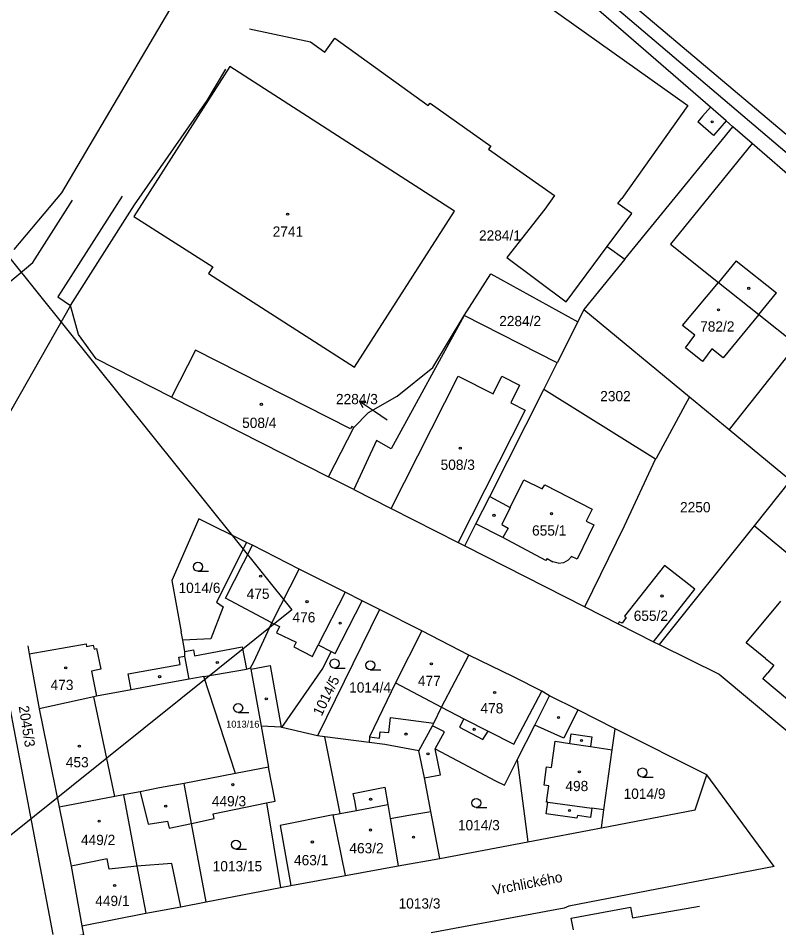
# Model space of a CAD drawing. Extents: x -793666 to -785424, y -1118958 to -1108761.
# Drawn here: x -791983.5 to -791857.2, y -1109795.1 to -1109644.2 of the extents above; entities that cross this region are included whole.
import ezdxf

# ---------------------------------------------------------------- set-up
doc = ezdxf.new("R2010")
doc.units = 0
for name, color, linetype in [('1_2000 - úřady', 7, 'Continuous'), ('Hranice parcel', 7, 'Continuous'), ('Parcelní čísla', 7, 'Continuous'), ('Pop  PČ popisy', 7, 'Continuous'), ('Vnitřní kresba', 7, 'Continuous'), ('Značky budov', 7, 'Continuous'), ('Značky kultur', 7, 'Continuous')]:
    doc.layers.add(name, color=color, linetype=linetype)

msp = doc.modelspace()

# ---------------------------------------------------------------- linework, layer by layer
at = {"layer": '1_2000 - úřady'}
msp.add_lwpolyline([(-791938.08, -1109742.36), (-792598.01, -1110271.46), (-792786.15, -1110036.8), (-792126.22, -1109507.7)], close=True, dxfattribs=at)
at = {"layer": 'Hranice parcel'}
for p, q in [((-791882.76, -1109684.15), (-791864.85, -1109662.19)), ((-791861.64, -1109664.97), (-791864.85, -1109662.19)), ((-791831.46, -1109691.13), (-791861.64, -1109664.97)), ((-791882.76, -1109684.15), (-791889.58, -1109692.5)), ((-791974.78, -1109691.82), (-791985.69, -1109711.05)), ((-791894.03, -1109701.35), (-791909.43, -1109693.51)), ((-791889.58, -1109692.5), (-791890.6, -1109694.54)), ((-791889.58, -1109692.5), (-791872.04, -1109706.99)), ((-791890.6, -1109694.54), (-791894.03, -1109701.35)), ((-791854.32, -1109698.31), (-791865.49, -1109712.41)), ((-791958, -1109707.05), (-791970.54, -1109700.7)), ((-791896.25, -1109705.77), (-791894.03, -1109701.35)), ((-791877.68, -1109717.35), (-791896.25, -1109705.77)), ((-791958, -1109707.05), (-791931.97, -1109720.25)), ((-791872.04, -1109706.99), (-791877.61, -1109717.21)), ((-791872.04, -1109706.99), (-791865.49, -1109712.41)), ((-791927.77, -1109712.09), (-791925.35, -1109709.61)), ((-791931.97, -1109720.25), (-791927.77, -1109712.09)), ((-791865.49, -1109712.41), (-791855.28, -1109720.85)), ((-791877.61, -1109717.21), (-791877.68, -1109717.35)), ((-791927.74, -1109722.4), (-791931.97, -1109720.25)), ((-791855.28, -1109720.85), (-791861.3, -1109728.39)), ((-791953.47, -1109727.24), (-791957.98, -1109737.48)), ((-791945.56, -1109731.16), (-791953.47, -1109727.24)), ((-791861.3, -1109728.39), (-791877.07, -1109748.13)), ((-791837.39, -1109748.55), (-791861.3, -1109728.39)), ((-791909.36, -1109731.72), (-791889.45, -1109741.84)), ((-791957.98, -1109737.48), (-791956.42, -1109746.03)), ((-791923.52, -1109742.28), (-791926.4, -1109740.83)), ((-791889.45, -1109741.84), (-791883.9, -1109744.66)), ((-791923.52, -1109742.28), (-791933.8, -1109763.25)), ((-791916.48, -1109745.84), (-791923.52, -1109742.28)), ((-791883.9, -1109744.66), (-791878.03, -1109747.64)), ((-791956.17, -1109747.38), (-791956.42, -1109746.03)), ((-791908.66, -1109749.89), (-791916.48, -1109745.84)), ((-791878.03, -1109747.64), (-791877.07, -1109748.13)), ((-791977.67, -1109796.24), (-791985.8, -1109753.42)), ((-791952.67, -1109753.41), (-791955.12, -1109753.87)), ((-791947.39, -1109769.52), (-791952.67, -1109753.41)), ((-791980, -1109758.8), (-791976.67, -1109775.1)), ((-791943.16, -1109761.65), (-791941.92, -1109768.48)), ((-791933.8, -1109763.25), (-791939.71, -1109761.86)), ((-791932.57, -1109763.41), (-791933.8, -1109763.25)), ((-791869.18, -1109769.73), (-791884.37, -1109762.08)), ((-791925.23, -1109764.37), (-791932.57, -1109763.41)), ((-791916.05, -1109770.26), (-791916.98, -1109765.74)), ((-791900.65, -1109767.25), (-791898.88, -1109780.87)), ((-791941.92, -1109768.48), (-791947.39, -1109769.52)), ((-791947.39, -1109769.52), (-791955.94, -1109771.15)), ((-791858, -1109784.94), (-791869.18, -1109769.73)), ((-791954.7, -1109777.79), (-791955.94, -1109771.15)), ((-791976.67, -1109775.1), (-791974.7, -1109784.87)), ((-791942.26, -1109774.38), (-791939.94, -1109788.43)), ((-791952.26, -1109790.84), (-791954.7, -1109777.79)), ((-791898.88, -1109780.87), (-791886.67, -1109778.56)), ((-791913.48, -1109783.61), (-791898.88, -1109780.87)), ((-791974.7, -1109784.87), (-791972.9, -1109794.78)), ((-791952.26, -1109790.84), (-791939.94, -1109788.43)), ((-791956.49, -1109791.62), (-791952.26, -1109790.84))]:
    msp.add_line(p, q, dxfattribs=at)
for points in [[(-791936.4, -1109607.05), (-791911, -1109616.98), (-791847.86, -1109670.26), (-791825.29, -1109690.56)], [(-791825.29, -1109690.56), (-791837.48, -1109682.19), (-791913.92, -1109617.19), (-791930.18, -1109620.63)], [(-791864.85, -1109662.19), (-791865.97, -1109661.2), (-791868.59, -1109658.92), (-791914.76, -1109618.89), (-791930.18, -1109620.63)], [(-791984.15, -1109682.54), (-791976.2, -1109673.16), (-791951.58, -1109631.36)], [(-791945.08, -1109645.94), (-791934.96, -1109648.1), (-791932.56, -1109649.82), (-791930.89, -1109647.49), (-791915.42, -1109658.67), (-791915.08, -1109658.25), (-791905.04, -1109665.4), (-791905.41, -1109665.89), (-791894.46, -1109673.59), (-791896.07, -1109675.85), (-791902.38, -1109683.85), (-791892.52, -1109691.21)], [(-791974.78, -1109691.82), (-791964.15, -1109675.11), (-791952.08, -1109657.83), (-791949.02, -1109652.63)], [(-791951.91, -1109686.53), (-791927.63, -1109702.08), (-791911.04, -1109676.18), (-791948.37, -1109652.16), (-791964.28, -1109677.07), (-791951.17, -1109685.45), (-791951.91, -1109686.53)], [(-791861.64, -1109664.97), (-791875.21, -1109681.64), (-791867.24, -1109688), (-791860.55, -1109693.34), (-791854.32, -1109698.31)], [(-791892.52, -1109691.21), (-791885.72, -1109682.06), (-791882.76, -1109684.15)], [(-791909.43, -1109693.51), (-791905.04, -1109686.57), (-791890.6, -1109694.54)], [(-791970.54, -1109700.7), (-791973.45, -1109696.66), (-791974.78, -1109691.82)], [(-791909.43, -1109693.51), (-791921.58, -1109715.65), (-791924.01, -1109714.23), (-791927.74, -1109722.4)], [(-791925.35, -1109709.61), (-791920.57, -1109706.88), (-791914.67, -1109702.14), (-791909.43, -1109693.51)], [(-791927.77, -1109712.09), (-791928.11, -1109711.92), (-791928.32, -1109712.31), (-791954.06, -1109699.28), (-791958, -1109707.05)], [(-791909.36, -1109731.72), (-791907.51, -1109728.09), (-791905.2, -1109723.56), (-791896.25, -1109705.77)], [(-791889.45, -1109741.84), (-791882.86, -1109728.42), (-791877.68, -1109717.35)], [(-791927.74, -1109722.4), (-791921.59, -1109725.52), (-791910.47, -1109731.16), (-791909.36, -1109731.72)], [(-791945.56, -1109731.16), (-791950.56, -1109741.08), (-791949.46, -1109741.85), (-791951.52, -1109747.16), (-791956.17, -1109747.38)], [(-791936.85, -1109735.6), (-791944.59, -1109731.64), (-791945.56, -1109731.16)], [(-791944.92, -1109751.98), (-791944.35, -1109750.98), (-791941.37, -1109744.5), (-791936.85, -1109735.6)], [(-791926.4, -1109740.83), (-791929.2, -1109739.43), (-791936.85, -1109735.6)], [(-791878.03, -1109747.64), (-791871.19, -1109738.94), (-791876.22, -1109735.02), (-791882.82, -1109743.38), (-791882.54, -1109743.62), (-791883.25, -1109744.54), (-791883.73, -1109744.32), (-791883.9, -1109744.66)], [(-791939.71, -1109761.86), (-791932.93, -1109752.07), (-791931.53, -1109749.25), (-791930.88, -1109749.58), (-791926.4, -1109740.83)], [(-791916.48, -1109745.84), (-791920.82, -1109754.46), (-791925.16, -1109763.43), (-791925.23, -1109764.37)], [(-791955.12, -1109753.87), (-791955.83, -1109750.03), (-791955.83, -1109749.27), (-791956.17, -1109747.38)], [(-791877.07, -1109748.13), (-791867.13, -1109753.04), (-791851.69, -1109765.91)], [(-791981.88, -1109748.34), (-791981.62, -1109749.67), (-791980, -1109758.8)], [(-791916.98, -1109765.74), (-791914.7, -1109761.63), (-791914.48, -1109761.17), (-791913.24, -1109758.52), (-791908.66, -1109749.89)], [(-791895.28, -1109756.65), (-791896.56, -1109755.87), (-791901.25, -1109753.47), (-791908.66, -1109749.89)], [(-791952.67, -1109753.41), (-791945.6, -1109752.19), (-791944.92, -1109751.98)], [(-791944.92, -1109751.98), (-791944.88, -1109752.2), (-791943.16, -1109761.65)], [(-791955.12, -1109753.87), (-791959.71, -1109754.71), (-791964.71, -1109755.64), (-791970.45, -1109756.7), (-791970.94, -1109756.81), (-791980, -1109758.8)], [(-791900.65, -1109767.25), (-791897.74, -1109761.51), (-791895.28, -1109756.65)], [(-791884.37, -1109762.08), (-791890.57, -1109758.96), (-791895.28, -1109756.65)], [(-791939.71, -1109761.86), (-791939.81, -1109761.85), (-791943.16, -1109761.65)], [(-791886.67, -1109778.56), (-791886.25, -1109775.56), (-791884.86, -1109765.59), (-791884.37, -1109762.08)], [(-791929.16, -1109786.47), (-791931.21, -1109776.4), (-791930.04, -1109776.18), (-791932.57, -1109763.41)], [(-791916.98, -1109765.74), (-791922.61, -1109764.71), (-791925.23, -1109764.37)], [(-791916.05, -1109770.26), (-791913.4, -1109769.73), (-791914.24, -1109765.44), (-791904.26, -1109770.74), (-791902.77, -1109771.45), (-791900.65, -1109767.25)], [(-791942.26, -1109774.38), (-791940.83, -1109774.08), (-791941.92, -1109768.48)], [(-791913.48, -1109783.61), (-791914.98, -1109775.8), (-791916.05, -1109770.26)], [(-791886.67, -1109778.56), (-791871.09, -1109775.55), (-791869.18, -1109769.73)], [(-791955.94, -1109771.15), (-791959.99, -1109771.92), (-791963.2, -1109772.53), (-791966.01, -1109773.07), (-791967.41, -1109773.34), (-791976.67, -1109775.1)], [(-791954.7, -1109777.79), (-791950.95, -1109776.97), (-791951.11, -1109776.23), (-791942.26, -1109774.38)], [(-791956.49, -1109791.62), (-791957.96, -1109784.45), (-791963.78, -1109784.91), (-791968.37, -1109785.42), (-791968.72, -1109783.66), (-791974.7, -1109784.87)], [(-791929.16, -1109786.47), (-791920.41, -1109784.85), (-791913.48, -1109783.61)], [(-791858, -1109784.94), (-791892.07, -1109791.53), (-791892.88, -1109791.84), (-791914.93, -1109795.98)], [(-791939.94, -1109788.43), (-791938.21, -1109788.12), (-791929.16, -1109786.47)], [(-791972.9, -1109794.78), (-791962.31, -1109792.7), (-791956.49, -1109791.62)], [(-791972.9, -1109794.78), (-791972.62, -1109796.28), (-791976.5, -1109797)]]:
    msp.add_lwpolyline(points, dxfattribs=at)
at = {"layer": 'Pop  PČ popisy'}
for p, q in [((-791924.32, -1109709.46), (-791926.81, -1109707.78)), ((-791926.81, -1109707.78), (-791925.7, -1109707.93)), ((-791926.81, -1109707.78), (-791926.26, -1109708.76)), ((-791922.22, -1109710.87), (-791924.32, -1109709.46))]:
    msp.add_line(p, q, dxfattribs=at)
at = {"layer": 'Vnitřní kresba'}
for p, q in [((-791913.19, -1109629.58), (-791872.34, -1109658.65)), ((-791872.34, -1109658.65), (-791883.31, -1109674.08)), ((-791869.88, -1109660.4), (-791868.59, -1109658.92)), ((-791869.88, -1109660.4), (-791870.69, -1109661.37)), ((-791868.07, -1109663.61), (-791870.69, -1109661.37)), ((-791865.97, -1109661.2), (-791868.07, -1109663.61)), ((-791966.24, -1109673.68), (-791976.88, -1109690.38)), ((-791883.93, -1109674.92), (-791883.31, -1109674.08)), ((-791981.02, -1109684.68), (-791974.45, -1109674.36)), ((-791881.65, -1109676.6), (-791883.93, -1109674.92)), ((-791885.72, -1109682.06), (-791881.65, -1109676.6)), ((-791988.67, -1109691.09), (-791981.02, -1109684.68)), ((-791864.28, -1109684.44), (-791867.24, -1109688)), ((-791864.28, -1109684.44), (-791857.59, -1109689.76)), ((-791873.2, -1109695.16), (-791867.24, -1109688)), ((-791976.88, -1109690.38), (-791974.78, -1109691.82)), ((-791860.55, -1109693.34), (-791857.59, -1109689.76)), ((-791860.55, -1109693.34), (-791866.49, -1109700.55)), ((-791871.18, -1109696.78), (-791873.2, -1109695.16)), ((-791872.73, -1109698.84), (-791871.18, -1109696.78)), ((-791869.91, -1109701.15), (-791872.73, -1109698.84)), ((-791868.36, -1109699.04), (-791869.91, -1109701.15)), ((-791866.49, -1109700.55), (-791868.36, -1109699.04)), ((-791921.59, -1109725.52), (-791910.47, -1109703.57)), ((-791910.47, -1109703.57), (-791904.65, -1109706.5)), ((-791904.65, -1109706.5), (-791903.19, -1109703.59)), ((-791903.19, -1109703.59), (-791900.25, -1109705.07)), ((-791900.25, -1109705.07), (-791901.71, -1109707.97)), ((-791901.71, -1109707.97), (-791899.3, -1109709.19)), ((-791899.3, -1109709.19), (-791910.47, -1109731.16)), ((-791901.82, -1109725.39), (-791899.54, -1109720.78)), ((-791899.54, -1109720.78), (-791896.48, -1109722.29)), ((-791896.48, -1109722.29), (-791896.05, -1109721.6)), ((-791896.05, -1109721.6), (-791888.22, -1109725.67)), ((-791905.2, -1109723.56), (-791901.82, -1109725.39)), ((-791901.82, -1109725.39), (-791903.21, -1109728.21)), ((-791888.22, -1109725.67), (-791889.23, -1109727.61)), ((-791903.01, -1109730.36), (-791907.51, -1109728.09)), ((-791903.21, -1109728.21), (-791902.16, -1109728.78)), ((-791902.16, -1109728.78), (-791903.01, -1109730.36)), ((-791949.07, -1109740.43), (-791944.59, -1109731.64)), ((-791895.7, -1109733.84), (-791894.73, -1109734.41)), ((-791893.84, -1109734.63), (-791894.73, -1109734.41)), ((-791893.84, -1109734.63), (-791892.89, -1109734.49)), ((-791892.89, -1109734.49), (-791892.11, -1109734.04)), ((-791891.63, -1109733.48), (-791892.11, -1109734.04)), ((-791890.7, -1109733.94), (-791891.63, -1109733.48)), ((-791941.37, -1109744.5), (-791949.07, -1109740.43)), ((-791929.2, -1109739.43), (-791933.67, -1109748.15)), ((-791862.67, -1109747.82), (-791856.87, -1109740.94)), ((-791941.37, -1109744.5), (-791940.11, -1109745.1)), ((-791940.11, -1109745.1), (-791940.62, -1109746.17)), ((-791940.62, -1109746.17), (-791937.33, -1109747.73)), ((-791981.62, -1109749.67), (-791972.2, -1109748)), ((-791972.2, -1109748), (-791972.11, -1109748.45)), ((-791937.33, -1109747.73), (-791937.7, -1109748.51)), ((-791934.65, -1109750.07), (-791933.67, -1109748.15)), ((-791933.67, -1109748.15), (-791931.53, -1109749.25)), ((-791859.45, -1109750.41), (-791862.67, -1109747.82)), ((-791972.11, -1109748.45), (-791971, -1109748.23)), ((-791971, -1109748.23), (-791970.87, -1109748.86)), ((-791970.87, -1109748.86), (-791970.47, -1109748.78)), ((-791970.47, -1109748.78), (-791969.73, -1109752.21)), ((-791955.83, -1109749.27), (-791954.4, -1109749.01)), ((-791954.4, -1109749.01), (-791954.21, -1109749.99)), ((-791954.21, -1109749.99), (-791946.32, -1109748.47)), ((-791946.32, -1109748.47), (-791945.6, -1109752.19)), ((-791937.7, -1109748.51), (-791934.65, -1109750.07)), ((-791956.82, -1109750.22), (-791955.83, -1109750.03)), ((-791956.61, -1109751.4), (-791956.82, -1109750.22)), ((-791859.45, -1109750.41), (-791858.06, -1109751.52)), ((-791969.73, -1109752.21), (-791971.29, -1109752.53)), ((-791971.29, -1109752.53), (-791970.45, -1109756.7)), ((-791965.21, -1109752.98), (-791956.61, -1109751.4)), ((-791944.88, -1109752.2), (-791941.65, -1109751.61)), ((-791941.65, -1109751.61), (-791939.81, -1109761.85)), ((-791858.06, -1109751.52), (-791859.07, -1109752.78)), ((-791964.71, -1109755.64), (-791965.21, -1109752.98)), ((-791859.87, -1109753.78), (-791859.07, -1109752.78)), ((-791852.28, -1109760.19), (-791859.87, -1109753.78)), ((-791920.82, -1109754.46), (-791913.24, -1109758.52)), ((-791967.41, -1109773.34), (-791970.94, -1109756.81)), ((-791901.21, -1109764.62), (-791896.56, -1109755.87)), ((-791913.24, -1109758.52), (-791909.5, -1109760.42)), ((-791921.94, -1109762.69), (-791921.7, -1109760.2)), ((-791921.7, -1109760.2), (-791914.48, -1109761.17)), ((-791890.57, -1109758.96), (-791892.91, -1109763.66)), ((-791912.7, -1109762.62), (-791914.7, -1109761.63)), ((-791909.5, -1109760.42), (-791910.25, -1109761.81)), ((-791909.5, -1109760.42), (-791905.47, -1109762.47)), ((-791892.91, -1109763.66), (-791897.74, -1109761.51)), ((-791923.53, -1109763.67), (-791923.38, -1109762.6)), ((-791923.38, -1109762.6), (-791921.94, -1109762.69)), ((-791914.24, -1109765.44), (-791912.7, -1109762.62)), ((-791910.25, -1109761.81), (-791906.34, -1109763.88)), ((-791906.34, -1109763.88), (-791905.47, -1109762.47)), ((-791905.47, -1109762.47), (-791901.21, -1109764.62)), ((-791891.93, -1109764.51), (-791891.69, -1109762.92)), ((-791891.69, -1109762.92), (-791888.25, -1109763.44)), ((-791925.16, -1109763.43), (-791923.53, -1109763.67)), ((-791894.95, -1109768.53), (-791894.33, -1109764.15)), ((-791894.33, -1109764.15), (-791891.93, -1109764.51)), ((-791891.93, -1109764.51), (-791888.49, -1109765.04)), ((-791888.25, -1109763.44), (-791888.49, -1109765.04)), ((-791888.49, -1109765.04), (-791884.86, -1109765.59)), ((-791896.2, -1109771.44), (-791895.77, -1109768.42)), ((-791895.77, -1109768.42), (-791894.95, -1109768.53)), ((-791927.86, -1109772.82), (-791922.63, -1109771.77)), ((-791922.63, -1109771.77), (-791922.14, -1109774.67)), ((-791895.38, -1109771.55), (-791896.2, -1109771.44)), ((-791895.77, -1109774.25), (-791895.38, -1109771.55)), ((-791966.01, -1109773.07), (-791963.78, -1109784.91)), ((-791963.2, -1109772.53), (-791961.89, -1109777.95)), ((-791927.61, -1109774.06), (-791927.86, -1109772.82)), ((-791927.32, -1109775.66), (-791927.61, -1109774.06)), ((-791927.32, -1109775.66), (-791922.14, -1109774.67)), ((-791922.14, -1109774.67), (-791921.74, -1109777.01)), ((-791895.85, -1109776.23), (-791895.58, -1109774.27)), ((-791895.58, -1109774.27), (-791895.77, -1109774.25)), ((-791895.58, -1109774.27), (-791888.26, -1109775.28)), ((-791888.26, -1109775.28), (-791888.47, -1109776.81)), ((-791886.25, -1109775.56), (-791888.26, -1109775.28)), ((-791931.21, -1109776.4), (-791939.98, -1109778.13)), ((-791930.04, -1109776.18), (-791927.32, -1109775.66)), ((-791921.74, -1109777.01), (-791918.63, -1109776.44)), ((-791918.63, -1109776.44), (-791914.98, -1109775.8)), ((-791890.73, -1109776.95), (-791895.85, -1109776.23)), ((-791890.66, -1109776.51), (-791890.73, -1109776.95)), ((-791888.47, -1109776.81), (-791890.66, -1109776.51)), ((-791961.89, -1109777.95), (-791958.69, -1109777.44)), ((-791958.69, -1109777.44), (-791958.41, -1109778.61)), ((-791958.41, -1109778.61), (-791954.7, -1109777.79)), ((-791939.98, -1109778.13), (-791938.21, -1109788.12)), ((-791921.74, -1109777.01), (-791920.41, -1109784.85)), ((-791963.78, -1109784.91), (-791962.31, -1109792.7)), ((-791891.67, -1109793.52), (-791881.84, -1109791.71)), ((-791881.84, -1109791.71), (-791881.51, -1109793.48)), ((-791881.51, -1109793.48), (-791870.39, -1109791.52)), ((-791891.31, -1109795.47), (-791891.67, -1109793.52))]:
    msp.add_line(p, q, dxfattribs=at)
for points in [[(-791889.23, -1109727.61), (-791887.92, -1109728.26), (-791890.7, -1109733.94)], [(-791895.7, -1109733.84), (-791895.88, -1109734.18), (-791903.01, -1109730.36)]]:
    msp.add_lwpolyline(points, dxfattribs=at)
at = {"layer": 'Značky budov'}
for centre in [(-791868.28, -1109661.36), (-791938.75, -1109676.67), (-791862.22, -1109689), (-791867.25, -1109692.55), (-791943.11, -1109708.24), (-791910.1, -1109715.52), (-791904.5, -1109726.66), (-791894.96, -1109726.39), (-791943.22, -1109736.77), (-791876.61, -1109740.05), (-791935.53, -1109741), (-791930.02, -1109744.55), (-791950.42, -1109751.1), (-791914.9, -1109751.32), (-791975.58, -1109751.98), (-791959.99, -1109753.44), (-791942.29, -1109757.13), (-791904.39, -1109756.08), (-791893.8, -1109760.23), (-791919.1, -1109762.97), (-791907.79, -1109762.19), (-791973.32, -1109764.99), (-791889.99, -1109764.04), (-791915.46, -1109766.24), (-791890.33, -1109769.23), (-791947.84, -1109771.37), (-791924.97, -1109773.79), (-791958.98, -1109774.95), (-791891.97, -1109775.67), (-791970.02, -1109777.44), (-791925, -1109778.9), (-791917.85, -1109780.07), (-791934.65, -1109780.88), (-791967.46, -1109788.09)]:
    msp.add_circle(centre, 0.175, dxfattribs=at)
at = {"layer": 'Značky kultur'}
for p, q in [((-791953.64, -1109735.96), (-791951.89, -1109735.96)), ((-791930.97, -1109752.01), (-791929.22, -1109752.01)), ((-791925.03, -1109752.29), (-791923.28, -1109752.29)), ((-791946.96, -1109759.39), (-791945.21, -1109759.39)), ((-791879.86, -1109770.1), (-791878.11, -1109770.1)), ((-791907.45, -1109775.16), (-791905.7, -1109775.16)), ((-791947.34, -1109782.06), (-791945.59, -1109782.06))]:
    msp.add_line(p, q, dxfattribs=at)
for centre in [(-791953.64, -1109735.21), (-791930.97, -1109751.26), (-791925.03, -1109751.54), (-791946.96, -1109758.64), (-791879.86, -1109769.35), (-791907.45, -1109774.41), (-791947.34, -1109781.31)]:
    msp.add_circle(centre, 0.75, dxfattribs=at)

# ---------------------------------------------------------------- texts
at = {"layer": 'Parcelní čísla'}
for s, height, p in [('2741', 1.7, (-791941.23, -1109680.42)), ('2284/1', 1.7, (-791906.99, -1109681.07)), ('2284/2', 1.7, (-791903.64, -1109695.27)), ('782/2', 1.7, (-791870.28, -1109696.17)), ('2284/3', 1.7, (-791930.73, -1109708.22)), ('2302', 1.7, (-791886.87, -1109707.73)), ('508/4', 1.7, (-791946.3, -1109712.16)), ('508/3', 1.7, (-791913.36, -1109719.12)), ('2250', 1.7, (-791873.62, -1109726.17)), ('655/1', 1.7, (-791898.18, -1109730.03)), ('1014/6', 1.7, (-791956.86, -1109739.55)), ('475', 1.7, (-791945.55, -1109740.53)), ('476', 1.7, (-791937.94, -1109744.44)), ('655/2', 1.7, (-791881.31, -1109744.18)), ('473', 1.7, (-791978.09, -1109755.66)), ('477', 1.7, (-791917.13, -1109754.99)), ('1014/4', 1.7, (-791928.54, -1109756.08)), ('478', 1.7, (-791906.74, -1109759.54)), ('1013/16', 1.14, (-791948.95, -1109761.9)), ('453', 1.7, (-791975.56, -1109768.49)), ('498', 1.7, (-791892.65, -1109772.44)), ('1014/9', 1.7, (-791882.99, -1109773.72)), ('449/3', 1.7, (-791951.33, -1109774.96)), ('1014/3', 1.7, (-791910.49, -1109778.94)), ('449/2', 1.7, (-791973.05, -1109781.39)), ('463/2', 1.7, (-791928.5, -1109782.76)), ('1013/15', 1.7, (-791951.19, -1109785.75)), ('463/1', 1.7, (-791937.69, -1109784.74)), ('449/1', 1.7, (-791970.68, -1109791.5)), ('1013/3', 1.7, (-791920.34, -1109791.93))]:
    msp.add_text(s, height=height, dxfattribs=at).set_placement(p)
for s, rotation, p in [('1014/5', 64, (-791933.12, -1109760.11)), ('2045/3', 279, (-791983.4, -1109758.38))]:
    msp.add_text(s, height=1.7, rotation=rotation, dxfattribs=at).set_placement(p)
at = {"layer": 'Pop  PČ popisy'}
msp.add_text('Vrchlického', height=1.7, rotation=11, dxfattribs=at).set_placement((-791904.56, -1109789.71))

doc.saveas('drawing.dxf')
